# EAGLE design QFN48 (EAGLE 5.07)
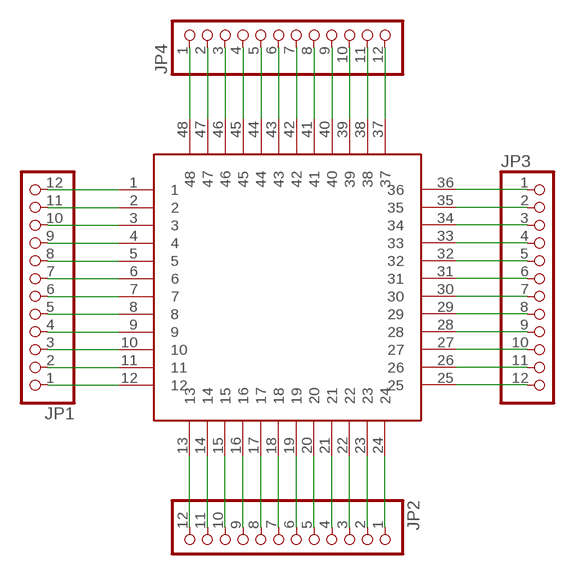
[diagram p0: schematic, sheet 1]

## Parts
JP1  PINHD-1X12  [1X12]
JP2  PINHD-1X12  [1X12]
JP3  PINHD-1X12  [1X12]
JP4  PINHD-1X12  [1X12]
U$1  48PIN  [QFN48]

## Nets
N$1: JP2.1 U$1.24
N$2: JP2.2 U$1.23
N$3: JP2.3 U$1.22
N$4: JP2.4 U$1.21
N$5: JP2.5 U$1.20
N$6: JP2.6 U$1.19
N$7: JP2.7 U$1.18
N$8: JP2.8 U$1.17
N$9: JP2.9 U$1.16
N$10: JP2.10 U$1.15
N$11: JP2.11 U$1.14
N$12: JP2.12 U$1.13
N$13: JP1.1 U$1.12
N$14: JP1.2 U$1.11
N$15: JP1.3 U$1.10
N$16: JP1.4 U$1.9
N$17: JP1.5 U$1.8
N$18: JP1.6 U$1.7
N$19: JP1.7 U$1.6
N$20: JP1.8 U$1.5
N$21: JP1.9 U$1.4
N$22: JP1.10 U$1.3
N$23: JP1.11 U$1.2
N$24: JP1.12 U$1.1
N$25: JP3.1 U$1.36
N$26: JP3.2 U$1.35
N$27: JP3.3 U$1.34
N$28: JP3.4 U$1.33
N$29: JP3.5 U$1.32
N$30: JP3.6 U$1.31
N$31: JP3.7 U$1.30
N$32: JP3.8 U$1.29
N$33: JP3.9 U$1.28
N$34: JP3.10 U$1.27
N$35: JP3.11 U$1.26
N$36: JP3.12 U$1.25
N$37: JP4.1 U$1.48
N$38: JP4.2 U$1.47
N$39: JP4.3 U$1.46
N$40: JP4.4 U$1.45
N$41: JP4.5 U$1.44
N$42: JP4.6 U$1.43
N$43: JP4.7 U$1.42
N$44: JP4.8 U$1.41
N$45: JP4.9 U$1.40
N$46: JP4.10 U$1.39
N$47: JP4.11 U$1.38
N$48: JP4.12 U$1.37

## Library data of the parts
JP1-JP4 = pinhead:PINHD-1X12: PIN HEADER
U$1 = generic-packages:48PIN

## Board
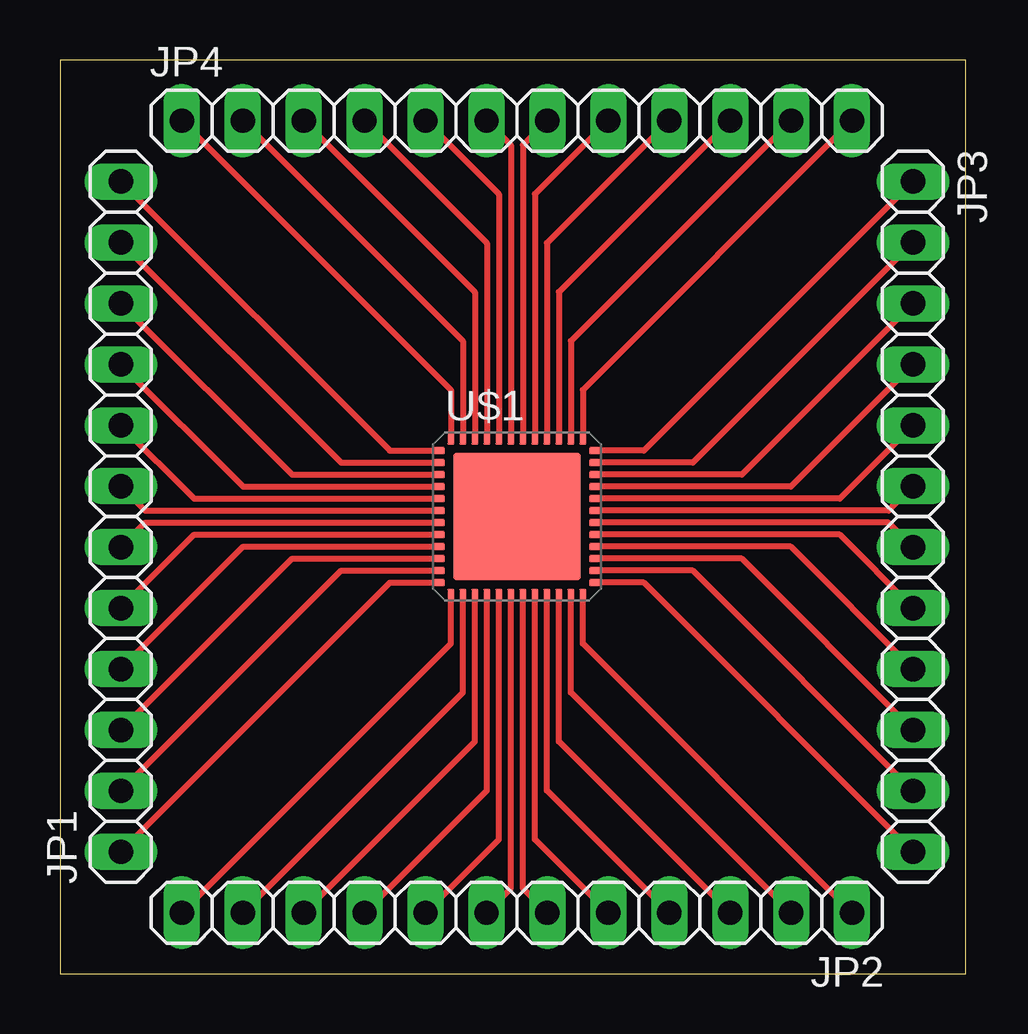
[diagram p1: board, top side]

Size 37.77 x 38.09 mm. Coordinates in mm from the lower left corner, seen from the top.
Outline: 0,0 37.77,0 37.77,38.09 0,38.09 0,0
Copper layers (1*16): Top 0.035mm / dielectric 1.5mm / Bottom 0.035mm
Design rules "default": minimum track width 10mil, minimum drill 24mil, track to track 8mil, track to pad 8mil, pad to pad 8mil, via to via 8mil, smd to smd 8mil, copper to edge 40mil, drill to drill 8mil, minimum pad ring 10mil, minimum via ring 8mil, stop-mask expansion 4mil, vias tented up to drill 0mil, thermal gap 10mil

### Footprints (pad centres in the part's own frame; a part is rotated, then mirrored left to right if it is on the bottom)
1X12 = drill 1.016 long: 1 -13.97,0; 2 -11.43,0; 3 -8.89,0; 4 -6.35,0; 5 -3.81,0; 6 -1.27,0; 7 1.27,0; 8 3.81,0; 9 6.35,0; 10 8.89,0; 11 11.43,0; 12 13.97,0
QFN48 = smd 0.55 x 0.3: 1 -3.275,2.75; 2 -3.275,2.25; 3 -3.275,1.75; 4 -3.275,1.25; 5 -3.275,0.75; 6 -3.275,0.25; 7 -3.275,-0.25; 8 -3.275,-0.75; 9 -3.275,-1.25; 10 -3.275,-1.75; 11 -3.275,-2.25; 12 -3.275,-2.75; 25 3.275,-2.75; 26 3.275,-2.25; 27 3.275,-1.75; 28 3.275,-1.25; 29 3.275,-0.75; 30 3.275,-0.25; 31 3.275,0.25; 32 3.275,0.75; 33 3.275,1.25; 34 3.275,1.75; 35 3.275,2.25; 36 3.275,2.75 | smd 0.3 x 0.55: 13 -2.75,-3.275; 14 -2.25,-3.275; 15 -1.75,-3.275; 16 -1.25,-3.275; 17 -0.75,-3.275; 18 -0.25,-3.275; 19 0.25,-3.275; 20 0.75,-3.275; 21 1.25,-3.275; 22 1.75,-3.275; 23 2.25,-3.275; 24 2.75,-3.275; 37 2.75,3.275; 38 2.25,3.275; 39 1.75,3.275; 40 1.25,3.275; 41 0.75,3.275; 42 0.25,3.275; 43 -0.25,3.275; 44 -0.75,3.275; 45 -1.25,3.275; 46 -1.75,3.275; 47 -2.25,3.275; 48 -2.75,3.275 | smd 5.309 x 5.309: EXP 0,0

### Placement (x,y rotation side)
JP1  2.54,19.05 90 top
JP2  19.05,2.54 180 top
JP3  35.56,19.05 270 top
JP4  19.05,35.56 0 top
U$1  19.05,19.05 0 top

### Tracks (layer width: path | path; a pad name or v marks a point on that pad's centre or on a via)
N$1
  Top 0.254: JP2.1 21.8,13.76 U$1.24
N$2
  Top 0.254: JP2.2 21.3,11.72 U$1.23
N$3
  Top 0.254: JP2.3 20.8,9.68 U$1.22
N$4
  Top 0.254: JP2.4 20.3,7.64 U$1.21
N$5
  Top 0.254: JP2.5 19.8,5.6 U$1.20
N$6
  Top 0.254: JP2.6 19.3,3.56 U$1.19
N$7
  Top 0.254: JP2.7 18.8,3.56 U$1.18
N$8
  Top 0.254: JP2.8 18.3,5.6 U$1.17
N$9
  Top 0.254: JP2.9 17.8,7.64 U$1.16
N$10
  Top 0.254: JP2.10 17.3,9.68 U$1.15
N$11
  Top 0.254: JP2.11 16.8,11.72 U$1.14
N$12
  Top 0.254: JP2.12 16.3,13.76 U$1.13
N$13
  Top 0.254: JP1.1 13.76,16.3 U$1.12
N$14
  Top 0.254: JP1.2 11.72,16.8 U$1.11
N$15
  Top 0.254: JP1.3 9.68,17.3 U$1.10
N$16
  Top 0.254: JP1.4 7.64,17.8 U$1.9
N$17
  Top 0.254: JP1.5 5.6,18.3 U$1.8
N$18
  Top 0.254: JP1.6 3.56,18.8 U$1.7
N$19
  Top 0.254: JP1.7 3.56,19.3 U$1.6
N$20
  Top 0.254: JP1.8 5.6,19.8 U$1.5
N$21
  Top 0.254: JP1.9 7.64,20.3 U$1.4
N$22
  Top 0.254: JP1.10 9.68,20.8 U$1.3
N$23
  Top 0.254: JP1.11 11.72,21.3 U$1.2
N$24
  Top 0.254: JP1.12 13.76,21.8 U$1.1
N$25
  Top 0.254: JP3.1 24.34,21.8 U$1.36
N$26
  Top 0.254: JP3.2 26.38,21.3 U$1.35
N$27
  Top 0.254: JP3.3 28.42,20.8 U$1.34
N$28
  Top 0.254: JP3.4 30.46,20.3 U$1.33
N$29
  Top 0.254: JP3.5 32.5,19.8 U$1.32
N$30
  Top 0.254: JP3.6 34.54,19.3 U$1.31
N$31
  Top 0.254: JP3.7 34.54,18.8 U$1.30
N$32
  Top 0.254: JP3.8 32.5,18.3 U$1.29
N$33
  Top 0.254: JP3.9 30.46,17.8 U$1.28
N$34
  Top 0.254: JP3.10 28.42,17.3 U$1.27
N$35
  Top 0.254: JP3.11 26.38,16.8 U$1.26
N$36
  Top 0.254: JP3.12 24.34,16.3 U$1.25
N$37
  Top 0.254: JP4.1 16.3,24.34 U$1.48
N$38
  Top 0.254: JP4.2 16.8,26.38 U$1.47
N$39
  Top 0.254: JP4.3 17.3,28.42 U$1.46
N$40
  Top 0.254: JP4.4 17.8,30.46 U$1.45
N$41
  Top 0.254: JP4.5 18.3,32.5 U$1.44
N$42
  Top 0.254: JP4.6 18.8,34.54 U$1.43
N$43
  Top 0.254: JP4.7 19.3,34.54 U$1.42
N$44
  Top 0.254: JP4.8 19.8,32.5 U$1.41
N$45
  Top 0.254: JP4.9 20.3,30.46 U$1.40
N$46
  Top 0.254: JP4.10 20.8,28.42 U$1.39
N$47
  Top 0.254: JP4.11 21.3,26.38 U$1.38
N$48
  Top 0.254: JP4.12 21.8,24.34 U$1.37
